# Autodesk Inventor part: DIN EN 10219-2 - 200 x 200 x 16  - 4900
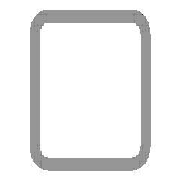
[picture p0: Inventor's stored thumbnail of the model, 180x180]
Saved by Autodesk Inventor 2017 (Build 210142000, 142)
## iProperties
IsCustomPart: 1
Created: 2017-11
Part Number: DIN EN 10219-2 - 200 x 200 x 16  - 4900
Material: Steel, Mild
Description: Cold formed welded structural hollow sections of non-alloy and fine grain structural steel
Document SubType Name: Modeling
Standard: DIN
Designer: iusti
Standard Revision: 2006-07
Standards Organization: DIN
Language: en-US
Size Designation: 200 x 200 x 16
Categories: <MemberInstance><Categories><Category DisplayName="Structural Shapes" InternalName="089c4875-fa83-4c05-b084-43b9cc11f5ed" Mnemonic="GRDR"><CategoryParameter Dis
Stock Number: 200 x 200 x 16
Density: 7.85 g/cm^3
Appearance: Semi-Polished
Mass: 410700 g
Surface Area: 65611.6 cm^2
Volume: 52318.5 cm^3
_CCFamilyMember: 103
_CCFamilyDisplayName: DIN EN 10219-2 (Square Hollow Section - Cold Formed) - Cold formed welded structural hollow sections of non-alloy and fine grain structural steel
_FrameMemberDoc: Frame Member File
_Version: 15.0.0
_GetPNFromCC: 1
G_L: 4900.000 mm
G_W: 200.000 mm
G_H: 200.000 mm
+3B88DE26-6118-40AC-AC7A-F683B1BCA643+CUTDETAIL1: Cut
Author: iusti
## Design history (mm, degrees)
node "Start plane"
node "End plane"
sketch "Sketch"
  geometry: L1 (-100, -52)-(-100, 52); L2 (-52, 100)-(52, 100); L3 (100, 52)-(100, -52); L4 (52, -100)-(-52, -100); L5 (-52, 84)-(52, 84); L6 (84, 52)-(84, -52); L7 (52, -84)-(-52, -84); L8 (-84, -52)-(-84, 52); L9 (0, 293.918)-(0, -293.918) reference; L10 (-293.918, 0)-(293.918, 0) reference; A1 r 48 centre (-52, -52) between (-100, -52) and (-52, -100); A2 r 48 centre (-52, 52) between (-52, 100) and (-100, 52); A3 r 48 centre (52, 52) between (100, 52) and (52, 100); A4 r 48 centre (52, -52) between (52, -100) and (100, -52); A5 r 32 centre (-52, 52) between (-52, 84) and (-84, 52); A6 r 32 centre (52, 52) between (84, 52) and (52, 84); A7 r 32 centre (52, -52) between (52, -84) and (84, -52); A8 r 32 centre (-52, -52) between (-84, -52) and (-52, -84)
  constraints: 16 end point, 16 point on circle, 8 centre point, 8 tangent, 4 parallel, 3 equal radius, 2 perpendicular, 7 other
  dimensions: "d7" = 48 radius of A1 (= G_IR); "d10" = 200 distance between parallel lines of L2 L4 (= G_H); "d11" = 200 distance between parallel lines of L1 L3 (= G_W); "d12" = 16 distance between parallel lines of L3 L6 (= G_T); "d15" = 100 distance between parallel lines of L2 L10 (= 0.5 x d10); "d16" = 100 distance between parallel lines of L9 L3 (= 0.5 x d11)
extrude "Body" new body sketch "Sketch" stored distance "d3" = 4900 (= G_L); taper "d4" = 0 deg
node "Driven Length"
  sketch "Sketch3"
    geometry: L1 (0, 0)-(10, 0) reference
    constraints: 2 end point, 1 horizontal
  workplane "Work Plane3"
  sketch "Sketch4"
    geometry: L1 (-2, 0)-(12, 0) reference; L2 (-2, 4900)-(12, 4900) reference
    dimensions: "d18" = 4900 distance between parallel lines of L1 L2 (derived)
workplane "Work Plane4"
split "Split1"
body "Solid1"
other parameters: "G_W" = 200 [user parameter; used in 1 equation term], "G_H" = 200 [user parameter; used in 1 equation term], "G_T" = 16 [user parameter; used in 1 equation term], "G_IR" = 48 [user parameter; used in 1 equation term], "G_L" = 4900 (= d18) [user parameter; used in 1 equation term], "G_OFFSET_START" = 0 [user parameter; used in 1 equation term], "d13" = 0 (computed from G_OFFSET_START), "d17" = 90 deg
